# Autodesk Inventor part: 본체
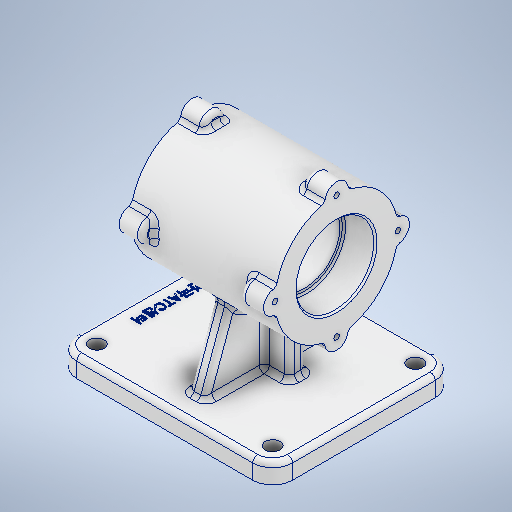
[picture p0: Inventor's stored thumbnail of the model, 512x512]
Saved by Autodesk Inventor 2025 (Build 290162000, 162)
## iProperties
Created: 2024-08
Part Number: 본체
Material: 알루미늄 6061
Document SubType Name: Modeling
Designer: 학생
Density: 2.7 g/cm^3
Appearance: 알루미늄 - 평지
Mass: 1217.77 g
Surface Area: 802.865 cm^2
Volume: 451.025 cm^3
Author: 학생
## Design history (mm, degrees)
sketch "스케치3"
  geometry: L1 (70, -55)-(70, 55); L2 (70, 55)-(-60, 55); L3 (-60, 55)-(-60, -55); L4 (-60, -55)-(70, -55); L5 (70, 0)-(140, 0); L6 (0, 0)-(70, 0)
  constraints: 12 end point, 2 horizontal, 2 horizontal alignment, 2 vertical alignment, 1 midpoint, 1 perpendicular, 1 vertical
  dimensions: "d6" = 110 distance of L2.end L3.end; "d10" = 70 distance of L5.start L6.start; "d11" = 130 distance between parallel lines of L1 L3
extrude "돌출1" new body sketch "스케치3" distance "d12" = 12; taper "d13" = 0 deg
sketch "스케치4"
  geometry: L1 (20, 5)-(-20, 5); L2 (-20, 5)-(-20, -5); L3 (-20, -5)-(20, -5); L4 (20, -5)-(20, 5); L5 (20, 5)-(-20, -5); L6 (-20, 5)-(20, -5); L7 (-5, 41)-(5, 41); L8 (5, 41)-(5, -41); L9 (5, -41)-(-5, -41); L10 (-5, -41)-(-5, 41); L11 (-5, 41)-(5, -41); L12 (5, 41)-(-5, -41); L13 (60, 55)-(-70, 55) reference; L14 (-70, -55)-(60, -55) reference; 6 further points
  constraints: 24 end point, 5 midpoint, 4 parallel, 2 horizontal, 2 perpendicular
  dimensions: "d14" = 10 distance of L1.end L2.end; "d15" = 10 distance of L8.end L9.end (= d14); "d16" = 40 distance of L1.start L1.end; "d17" = 82 distance of L7.end L8.end; "d18" = 14 distance from line of L13 point (0, 41) (derived); "d19" = 14 distance between parallel lines of L14 L9 (derived)
extrude "돌출2" join sketch "스케치4" distance "d20" = 60; taper "d21" = 0 deg
sketch "스케치5"
  geometry: L1 (0, 0)-(0, 82); L2 (-211.195, 82)-(211.195, 82); L3 (43.5, 45)-(-43.5, 45); L4 (-43.5, 45)-(-43.5, 119); L5 (-43.5, 119)-(43.5, 119); L6 (43.5, 119)-(43.5, 45); L7 (43.5, 45)-(-43.5, 119); L8 (-43.5, 45)-(43.5, 119); L9 (-43.5, 82)-(43.5, 82); 1 further point
  constraints: 18 end point, 4 midpoint, 2 horizontal, 2 parallel, 1 coincident, 1 perpendicular, 1 vertical
  dimensions: "d22" = 82 distance of L1.end L1.start; "d24" = 74 distance between parallel lines of L3 L5; "d27" = 87 distance of L4.end L5.end
revolve "회전1" sketch "스케치5" stored, may be unused: angle "d28" = 90 deg
feature "면 기울기1" dims angle "d29" = 20 deg
fillet "모깎기1" dims "d30" = 12
sketch "스케치6"
  geometry: L1 (-37, 0)-(37, 0); L2 (0, 37)-(0, -37); C1 r 7 at (0, 37); C2 r 7 at (-37, 0); C3 r 7 at (0, -37); C4 r 7 at (37, 0); A1 r 37 centre (0, 0) between (0, 37) and (-37, 0) reference; 3 further points
  constraints: 4 centre point, 4 end point, 4 midpoint, 4 point on circle, 3 equal radius, 1 horizontal, 1 vertical
  dimensions: "d31" = 14 diameter of C1
extrude "돌출3" join sketch "스케치6" distance "d32" = 14; taper "d33" = 0 deg
fillet "모깎기2" dims "d34" = 3
fillet "모깎기3" dims "d35" = 3
sketch "스케치7"
  geometry: L1 (-43.5, 91.104)-(-43.5, 117.863) reference; L2 (-43.5, 91.104)-(-32.5, 91.104) reference; L3 (-43.5, 91.104)-(-43.5, 117.863) reference; L4 (-32.5, 117.863)-(-43.5, 117.863) reference; L5 (-26.5, 118.912)-(-26.5, 118.913) reference; L6 (-43.5, 117.863)-(-32.5, 117.862) reference; L7 (-43.5, 117.863)-(-43.5, 91.104) reference; L8 (-32.5, 91.104)-(-43.5, 91.104) reference; L9 (-26.5, 79.457)-(-26.5, 84.543) reference; L10 (-43.5, 72.896)-(-32.5, 72.896) reference; L11 (-43.5, 72.896)-(-43.5, 46.138) reference; L12 (-32.5, 46.138)-(-43.5, 46.138) reference; L13 (-26.5, 45.088)-(-26.5, 45.088) reference; L14 (-43.5, 46.138)-(-32.5, 46.138) reference; L15 (-43.5, 46.138)-(-43.5, 72.896) reference; L16 (-32.5, 72.896)-(-43.5, 72.896) reference; L17 (-26.5, 84.543)-(-26.5, 79.457) reference; L18 (43.5, 72.896)-(32.5, 72.896) reference; L19 (43.5, 46.138)-(43.5, 72.896) reference; L20 (32.5, 46.138)-(43.5, 46.138) reference; L21 (26.5, 45.088)-(26.5, 45.088) reference; L22 (43.5, 46.138)-(32.5, 46.138) reference; L23 (43.5, 72.896)-(43.5, 46.138) reference; L24 (32.5, 72.896)-(43.5, 72.896) reference; L25 (26.5, 84.543)-(26.5, 79.457) reference; L26 (43.5, 91.104)-(32.5, 91.104) reference; L27 (43.5, 117.863)-(43.5, 91.104) reference; L28 (32.5, 117.862)-(43.5, 117.863) reference; L29 (26.5, 118.912)-(26.5, 118.912) reference; L30 (43.5, 117.863)-(32.5, 117.862) reference; L31 (43.5, 91.104)-(43.5, 117.863) reference; L32 (32.5, 91.104)-(43.5, 91.104) reference; L33 (26.5, 79.457)-(26.5, 84.543) reference; L34 (-5, 55.036)-(5, 55.036) reference; L35 (-5, 45.339)-(-5, 55.036) reference; L36 (-20, 45.339)-(-5, 45.339) reference; L37 (-20, 45.339)-(-20, 45.339) reference; L38 (-5, 45.339)-(-20, 45.339) reference; L39 (-5, 55.036)-(-5, 45.339) reference; L40 (-5, 55.036)-(5, 55.036) reference; L41 (5, 45.339)-(5, 55.036) reference; L42 (20, 45.339)-(5, 45.339) reference; L43 (20, 45.339)-(20, 45.339) reference; L44 (5, 45.339)-(20, 45.339) reference; L45 (5, 55.036)-(5, 45.339) reference; L46 (-43.5, 88.889)-(-43.5, 75.111) reference; L47 (-43.5, 82)-(43.5, 82); L48 (43.5, 88.889)-(43.5, 75.111) reference; L49 (-24.5, 58.5)-(-43.5, 58.5); L50 (-43.5, 58.5)-(-43.5, 82); L51 (-43.5, 82)-(-24.5, 82); L52 (-24.5, 82)-(-24.5, 58.5); L53 (-24.5, 58.5)-(-43.5, 82); L54 (-43.5, 58.5)-(-24.5, 82); L55 (43.5, 58.5)-(24.5, 58.5); L56 (24.5, 58.5)-(24.5, 82); L57 (24.5, 82)-(43.5, 82); L58 (43.5, 82)-(43.5, 58.5); L59 (43.5, 58.5)-(24.5, 82); L60 (24.5, 58.5)-(43.5, 82); L61 (24.5, 61)-(-24.5, 61); L62 (-24.5, 61)-(-24.5, 82); L63 (-24.5, 82)-(24.5, 82); L64 (24.5, 82)-(24.5, 61)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; 9 further points
  constraints: 38 end point, 8 midpoint, 6 parallel, 3 collinear, 3 horizontal, 3 perpendicular, 16 other
  dimensions: "d36" = 19 distance of L47.start L51.end; "d37" = 19 distance of L47.end L56.end (= d36); "d38" = 23.5 distance of L47.start L49.end; "d39" = 23.5 distance of L55.end L56.end (= d38); "d40" = 21 distance of L61.end L62.end
revolve "회전2" sketch "스케치7" stored, may be unused: angle "d41" = 90 deg
fillet "모깎기4" dims "d42" = 1
feature "결합1"
  node "솔리드2"
chamfer "모따기1" distance "d43" = 1; stored, may be unused: second distance "d44" = 2, angle "d45" = 45 deg
chamfer "모따기2" distance "d46" = 1; stored, may be unused: second distance "d47" = 2, angle "d48" = 45 deg
sketch "스케치8"
  geometry: C1 r 24.5 at (-37, 0) reference; A1 r 7 centre (-37, 37) between (-30.111, 38.239) and (-43.889, 38.239) reference; A2 r 7 centre (-74, 0) between (-75.239, 6.889) and (-75.239, -6.889) reference; A3 r 7 centre (-37, -37) between (-43.889, -38.239) and (-30.111, -38.239) reference; A4 r 7 centre (0, 0) between (1.239, -6.889) and (1.239, 6.889) reference; 5 further points
  constraints: 4 coincident, 2 horizontal alignment
hole "구멍1" sketch "스케치8" at (-37, 37), (-74, 0), (-37, -37), (0, 0) diameter "d49" = 3.242; stored, may be unused: countersink angle "d53" = 90 deg, drill point angle "d55" = 120 deg; dims "d50" = 8, "d51" = 4, "d52" = 2, "d54" = 10
fillet "모깎기5" dims "d60" = 3
fillet "모깎기6" dims "d61" = 3
sketch "스케치9"
  geometry: L1 (60, -43)-(60, 43) reference; A1 r 12 centre (-58, 43) between (-58, 55) and (-70, 43) reference; A2 r 12 centre (-58, -43) between (-70, -43) and (-58, -55) reference; A3 r 12 centre (48, -43) between (48, -55) and (60, -43) reference; 5 further points
  constraints: 3 coincident, 1 horizontal alignment, 1 vertical alignment
  dimensions: "d69" = 12 distance from line of L1 point (48, 43) (derived); "d70" = 86 distance of point (48, -43) point (48, 43) (derived)
hole "구멍2" sketch "스케치9" at (-58, 43), (-58, -43), (48, -43), (48, 43) diameter "d62" = 9; stored, may be unused: countersink angle "d66" = 90 deg, drill point angle "d68" = 0 deg; dims "d63" = 8, "d64" = 4, "d65" = 2, "d67" = 10
sketch "스케치10"
  geometry: 2 further points
  constraints: 1 horizontal alignment, 1 other
  dimensions: "d71" = 58 distance of point (0, 0) point (-58, 0)
feature "엠보싱1" sketch "스케치10" dims "d6" = 110, "d10" = 70, "d11" = 130, "d72" = 0.5, "d73" = 0
fillet "모깎기7" dims "d74" = 3
feature "Ձ耀Ճ耀Յ耀Շ耀Չ耀Ջ耀Ս耀Տ耀" dims "d6" = 110, "d10" = 70, "d11" = 130, "d12" = 12, "d13" = 0, "d14" = 10, "d15" = 10 (= d14), "d16" = 40, "d17" = 82, "d18" = 14 (derived), "d19" = 14 (derived), "d20" = 60, "d21" = 0, "d22" = 82, "d24" = 74, "d27" = 87, "d28" = 90 deg, "d29" = 20 deg, "d30" = 12, "d31" = 14, "d32" = 14, "d33" = 0, "d34" = 3, "d35" = 3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
node "솔리드1"
mirror "미러1"
mirror "미러2"
node "투영된 루프1"
feature "A9D066F2-1C7D-4E18-AEED-F7BC21143FA4" dims "d62" = 9, "d63" = 8, "d64" = 4, "d65" = 2, "d66" = 90 deg, "d67" = 10, "d68" = 0
